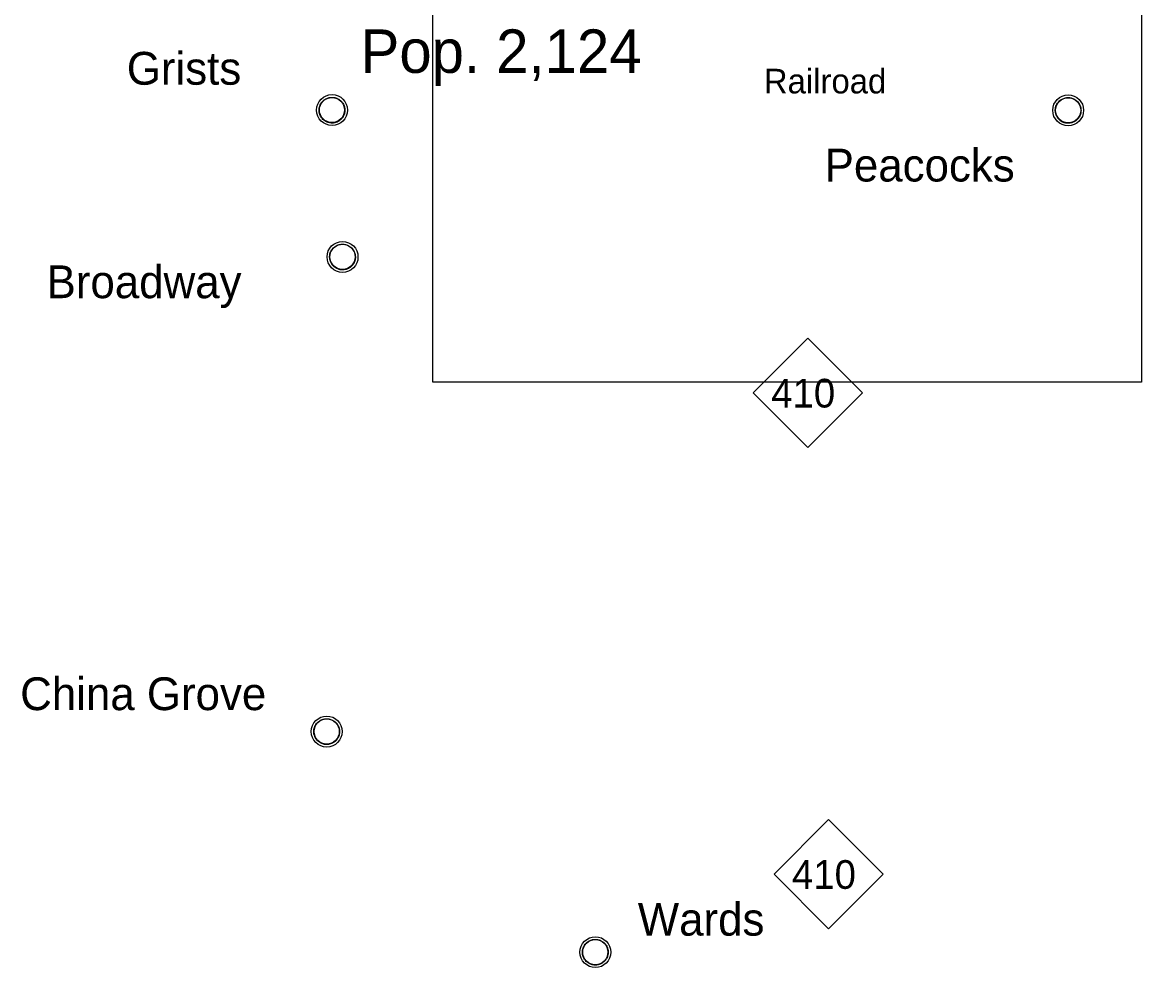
# Model space of a CAD drawing. Extents: x 5197761 to 5514561, y 1890130 to 2080942.
# Drawn here: x 5265672 to 5292986, y 1988805 to 2011870 of the extents above; entities that cross this region are included whole.
import ezdxf

# ---------------------------------------------------------------- set-up
doc = ezdxf.new("R2010")
doc.units = 0
for name, color, linetype in [('Exist Civil Demographics City Label', 7, 'Continuous'), ('Exist Civil Demographics Community CELL', 7, 'Continuous'), ('Exist Civil Demographics Community Label', 7, 'Continuous'), ('Exist Railroad Mainline Label', 7, 'Continuous'), ('Exist Road Primary NC Shield CELL', 7, 'Continuous'), ('Exist Road Primary NC Shield Number Label', 7, 'Continuous'), ('Map Preparation Inset Cut Line', 7, 'Continuous')]:
    doc.layers.add(name, color=color, linetype=linetype)

msp = doc.modelspace()

# ---------------------------------------------------------------- linework, layer by layer
at = {"layer": 'Exist Civil Demographics Community CELL'}
for points in [[(5272918, 2009780), (5272922, 2009802), (5272929, 2009828), (5272941, 2009857), (5272953, 2009880), (5272966, 2009903), (5272981, 2009923), (5272997, 2009941), (5273015, 2009959), (5273037, 2009978), (5273059, 2009992), (5273079, 2010004), (5273099, 2010013), (5273121, 2010023), (5273143, 2010030), (5273160, 2010035), (5273180, 2010038), (5273196, 2010040), (5273222, 2010041), (5273240, 2010041), (5273262, 2010040), (5273282, 2010037), (5273301, 2010033), (5273321, 2010027), (5273342, 2010020), (5273369, 2010008), (5273394, 2009994), (5273414, 2009980), (5273435, 2009964), (5273448, 2009951), (5273464, 2009934), (5273480, 2009915), (5273492, 2009897), (5273505, 2009877), (5273515, 2009856), (5273523, 2009836), (5273529, 2009816), (5273534, 2009797), (5273538, 2009773), (5273541, 2009754), (5273542, 2009730), (5273541, 2009707), (5273539, 2009685), (5273535, 2009663), (5273529, 2009638), (5273521, 2009615), (5273512, 2009594), (5273499, 2009570), (5273486, 2009549), (5273472, 2009530), (5273455, 2009511), (5273434, 2009492), (5273414, 2009475), (5273394, 2009461), (5273377, 2009451), (5273350, 2009438), (5273321, 2009427), (5273297, 2009422), (5273271, 2009416), (5273253, 2009414), (5273235, 2009413), (5273213, 2009413), (5273196, 2009415), (5273173, 2009418), (5273149, 2009423), (5273131, 2009428), (5273110, 2009436), (5273092, 2009444), (5273076, 2009453), (5273049, 2009469), (5273027, 2009486), (5273007, 2009504), (5272989, 2009524), (5272977, 2009540), (5272965, 2009556), (5272948, 2009585), (5272941, 2009599), (5272935, 2009615), (5272924, 2009648), (5272918, 2009676), (5272915, 2009696), (5272914, 2009722), (5272914, 2009740), (5272916, 2009766)], [(5290883, 2009773), (5290887, 2009796), (5290894, 2009822), (5290906, 2009851), (5290918, 2009874), (5290931, 2009897), (5290946, 2009917), (5290962, 2009935), (5290980, 2009953), (5291002, 2009971), (5291024, 2009986), (5291044, 2009997), (5291064, 2010007), (5291086, 2010016), (5291108, 2010024), (5291126, 2010028), (5291145, 2010031), (5291161, 2010034), (5291187, 2010035), (5291205, 2010035), (5291227, 2010034), (5291247, 2010031), (5291267, 2010027), (5291287, 2010021), (5291307, 2010013), (5291334, 2010002), (5291359, 2009988), (5291379, 2009974), (5291400, 2009958), (5291413, 2009945), (5291430, 2009928), (5291445, 2009909), (5291457, 2009890), (5291470, 2009870), (5291480, 2009850), (5291488, 2009830), (5291494, 2009810), (5291499, 2009791), (5291504, 2009767), (5291506, 2009748), (5291507, 2009724), (5291506, 2009701), (5291504, 2009678), (5291500, 2009656), (5291494, 2009632), (5291486, 2009608), (5291477, 2009588), (5291464, 2009564), (5291451, 2009543), (5291437, 2009524), (5291421, 2009505), (5291399, 2009485), (5291379, 2009469), (5291359, 2009455), (5291342, 2009445), (5291315, 2009432), (5291286, 2009421), (5291262, 2009415), (5291236, 2009410), (5291218, 2009408), (5291200, 2009407), (5291178, 2009407), (5291161, 2009409), (5291138, 2009412), (5291115, 2009417), (5291096, 2009422), (5291076, 2009430), (5291057, 2009438), (5291042, 2009447), (5291014, 2009463), (5290992, 2009480), (5290972, 2009498), (5290955, 2009517), (5290942, 2009533), (5290930, 2009550), (5290913, 2009578), (5290907, 2009593), (5290900, 2009609), (5290889, 2009641), (5290883, 2009670), (5290881, 2009690), (5290879, 2009715), (5290879, 2009734), (5290881, 2009760)], [(5273174, 2006196), (5273178, 2006219), (5273186, 2006245), (5273197, 2006274), (5273209, 2006297), (5273222, 2006320), (5273237, 2006340), (5273253, 2006358), (5273272, 2006376), (5273294, 2006394), (5273315, 2006409), (5273335, 2006420), (5273355, 2006430), (5273377, 2006439), (5273399, 2006447), (5273417, 2006451), (5273436, 2006454), (5273453, 2006457), (5273478, 2006458), (5273496, 2006458), (5273519, 2006457), (5273538, 2006454), (5273558, 2006450), (5273578, 2006444), (5273598, 2006437), (5273625, 2006425), (5273650, 2006411), (5273670, 2006397), (5273691, 2006381), (5273704, 2006368), (5273721, 2006351), (5273736, 2006332), (5273749, 2006313), (5273761, 2006293), (5273771, 2006273), (5273779, 2006253), (5273785, 2006233), (5273790, 2006214), (5273795, 2006190), (5273797, 2006171), (5273798, 2006147), (5273798, 2006124), (5273795, 2006101), (5273792, 2006079), (5273785, 2006055), (5273777, 2006031), (5273768, 2006011), (5273756, 2005987), (5273742, 2005966), (5273729, 2005947), (5273712, 2005928), (5273691, 2005908), (5273671, 2005892), (5273651, 2005878), (5273633, 2005868), (5273606, 2005855), (5273577, 2005844), (5273554, 2005838), (5273527, 2005833), (5273509, 2005831), (5273491, 2005830), (5273469, 2005830), (5273452, 2005832), (5273430, 2005835), (5273406, 2005840), (5273387, 2005845), (5273367, 2005853), (5273348, 2005861), (5273333, 2005870), (5273306, 2005886), (5273283, 2005903), (5273264, 2005921), (5273246, 2005940), (5273233, 2005956), (5273221, 2005973), (5273205, 2006001), (5273198, 2006016), (5273191, 2006032), (5273181, 2006064), (5273174, 2006093), (5273172, 2006113), (5273170, 2006138), (5273170, 2006157), (5273172, 2006183)], [(5272788, 1994614), (5272792, 1994637), (5272799, 1994663), (5272811, 1994692), (5272823, 1994715), (5272836, 1994738), (5272851, 1994758), (5272867, 1994776), (5272885, 1994794), (5272907, 1994813), (5272929, 1994827), (5272949, 1994839), (5272969, 1994848), (5272991, 1994858), (5273013, 1994865), (5273031, 1994870), (5273050, 1994872), (5273066, 1994875), (5273092, 1994876), (5273110, 1994876), (5273132, 1994875), (5273152, 1994872), (5273172, 1994868), (5273192, 1994862), (5273212, 1994855), (5273239, 1994843), (5273264, 1994829), (5273284, 1994815), (5273305, 1994799), (5273318, 1994786), (5273335, 1994769), (5273350, 1994750), (5273362, 1994732), (5273375, 1994712), (5273385, 1994691), (5273393, 1994671), (5273399, 1994651), (5273404, 1994632), (5273409, 1994608), (5273411, 1994589), (5273412, 1994565), (5273411, 1994542), (5273409, 1994520), (5273405, 1994498), (5273399, 1994473), (5273391, 1994450), (5273382, 1994429), (5273369, 1994405), (5273356, 1994384), (5273342, 1994365), (5273326, 1994346), (5273304, 1994326), (5273284, 1994310), (5273264, 1994296), (5273247, 1994286), (5273220, 1994273), (5273191, 1994262), (5273167, 1994257), (5273141, 1994251), (5273123, 1994249), (5273105, 1994248), (5273083, 1994248), (5273066, 1994250), (5273043, 1994253), (5273020, 1994258), (5273001, 1994263), (5272981, 1994271), (5272962, 1994279), (5272947, 1994288), (5272919, 1994304), (5272897, 1994321), (5272877, 1994339), (5272859, 1994359), (5272847, 1994374), (5272835, 1994391), (5272818, 1994420), (5272812, 1994434), (5272805, 1994450), (5272794, 1994483), (5272788, 1994511), (5272786, 1994531), (5272784, 1994557), (5272784, 1994575), (5272786, 1994601)], [(5279345, 1989232), (5279349, 1989254), (5279356, 1989281), (5279367, 1989309), (5279379, 1989332), (5279392, 1989355), (5279407, 1989376), (5279423, 1989393), (5279442, 1989412), (5279464, 1989430), (5279485, 1989445), (5279505, 1989456), (5279525, 1989466), (5279547, 1989475), (5279570, 1989482), (5279587, 1989487), (5279606, 1989490), (5279623, 1989493), (5279648, 1989494), (5279666, 1989493), (5279689, 1989492), (5279708, 1989489), (5279728, 1989486), (5279748, 1989480), (5279769, 1989472), (5279795, 1989460), (5279820, 1989446), (5279841, 1989432), (5279861, 1989416), (5279874, 1989404), (5279891, 1989386), (5279906, 1989367), (5279919, 1989349), (5279931, 1989329), (5279941, 1989308), (5279949, 1989288), (5279955, 1989268), (5279961, 1989250), (5279965, 1989226), (5279967, 1989207), (5279968, 1989183), (5279968, 1989160), (5279965, 1989137), (5279962, 1989115), (5279955, 1989090), (5279948, 1989067), (5279938, 1989047), (5279926, 1989023), (5279913, 1989001), (5279899, 1988983), (5279882, 1988964), (5279861, 1988944), (5279841, 1988927), (5279821, 1988914), (5279803, 1988904), (5279776, 1988891), (5279748, 1988880), (5279724, 1988874), (5279697, 1988869), (5279680, 1988867), (5279662, 1988866), (5279639, 1988866), (5279622, 1988868), (5279600, 1988870), (5279576, 1988876), (5279558, 1988881), (5279537, 1988888), (5279519, 1988896), (5279503, 1988905), (5279476, 1988922), (5279453, 1988939), (5279434, 1988957), (5279416, 1988976), (5279403, 1988992), (5279391, 1989009), (5279375, 1989037), (5279368, 1989051), (5279361, 1989067), (5279351, 1989100), (5279345, 1989128), (5279342, 1989149), (5279341, 1989174), (5279340, 1989193), (5279343, 1989219)]]:
    msp.add_lwpolyline(points, close=True, dxfattribs=at)
for centre, radius in [((5273229, 2009730), 377), ((5273227, 2009731), 307), ((5291194, 2009724), 377), ((5291193, 2009725), 307), ((5273485, 2006147), 377), ((5273484, 2006148), 307), ((5273099, 1994565), 377), ((5273098, 1994566), 307), ((5279655, 1989182), 377), ((5279654, 1989183), 307)]:
    msp.add_circle(centre, radius, dxfattribs=at)
at = {"layer": 'Exist Road Primary NC Shield CELL'}
for points in [[(5283509, 2002831), (5284841, 2004163), (5286173, 2002831), (5284841, 2001499)], [(5284016, 1991086), (5285348, 1992418), (5286680, 1991086), (5285348, 1989754)]]:
    msp.add_lwpolyline(points, close=True, dxfattribs=at)
at = {"layer": 'Map Preparation Inset Cut Line'}
msp.add_lwpolyline([(5275692, 2018349), (5292986, 2018349), (5292986, 2003094), (5275692, 2003094)], close=True, dxfattribs=at)

# ---------------------------------------------------------------- texts
at = {"layer": 'Exist Civil Demographics City Label'}
msp.add_text('Pop. 2,124', height=1060, dxfattribs=at).set_placement((5273926, 2010638))
at = {"layer": 'Exist Civil Demographics Community Label'}
for s, p in [('Grists', (5268220, 2010349)), ('Peacocks', (5285251, 2007987)), ('Broadway', (5266263, 2005140)), ('China Grove', (5265618, 1995088)), ('Wards', (5280690, 1989585))]:
    msp.add_text(s, height=800, dxfattribs=at).set_placement(p)
at = {"layer": 'Exist Railroad Mainline Label'}
msp.add_text('Railroad', height=600, rotation=359.9858, dxfattribs=at).set_placement((5283767, 2010137))
at = {"layer": 'Exist Road Primary NC Shield Number Label'}
for p in [(5283946, 2002472), (5284452, 1990727)]:
    msp.add_text('410', height=700, dxfattribs=at).set_placement(p)

doc.saveas('drawing.dxf')
